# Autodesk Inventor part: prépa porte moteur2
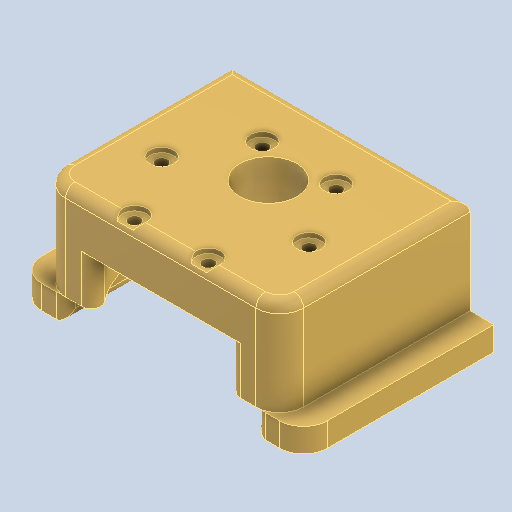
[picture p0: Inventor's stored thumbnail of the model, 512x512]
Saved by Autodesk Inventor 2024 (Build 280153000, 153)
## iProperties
Created: 2026-03
Part Number: prépa porte moteur2
Material: Acier
Document SubType Name: Modeling
Designer: bruno
Density: 7.85 g/cm^3
Appearance: Par défaut
Title: prpa porte moteur2.stp
Author: mel
Sending System: Autodesk Inventor 2026
Preprocessor: ST-DEVELOPER v20.1
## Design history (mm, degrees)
feature "Solide1"
node "Solide2"
